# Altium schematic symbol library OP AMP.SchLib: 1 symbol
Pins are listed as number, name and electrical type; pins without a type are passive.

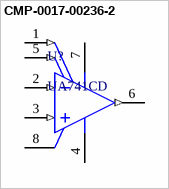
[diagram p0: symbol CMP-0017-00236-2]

## CMP-0017-00236-2
designator U?, comment UA741CD
General-Purpose Operational Amplifier, 7 to 36 V, 0 to 70 degC, 8-pin SOIC (D8), Green (RoHS & no Sb/Br); Manufacturer: Texas Instruments; Total Supply Voltage(Max)(+5V is 5, +/-5V is 10): 36; Number of Channels: 1; Total Supply Voltage(Min)(+5V is 5, +/-5V is 10): 7; Iq per channel(Max)(mA): 2.8; Slew Rate(Typ)(V/us): 0.5; Vio (25C)(Max)(mV): 6; Sub Family: General Purpose Amplifier, High Supply Voltage Amplifier (>=30V); CMRR(Min)(dB): 70; IIB(Max)(pA): 800000
footprint D0008A_N (SOIC, 8-Leads, Body 5x4mm, Pitch 1.27mm, IPC Medium Density)
footprint D0008A_L (SOIC, 8-Leads, Body 5x4mm, Pitch 1.27mm, IPC High Density)
footprint D0008A_M (SOIC, 8-Leads, Body 5x4mm, Pitch 1.27mm, IPC Low Density)
pins: 1 OFFSET N1 (in), 2 IN- (in), 3 IN+ (in), 4 VCC- (power), 5 OFFSET N2 (in), 6 OUT (out), 7 VCC+ (power), 8 NC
